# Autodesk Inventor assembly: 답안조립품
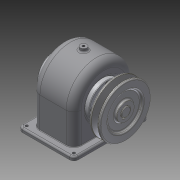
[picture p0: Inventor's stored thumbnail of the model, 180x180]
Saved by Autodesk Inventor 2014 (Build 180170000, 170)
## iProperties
Created: 2016-01
Part Number: 답안조립품
Document SubType Name: Assembly
Designer: basic
Author: basic
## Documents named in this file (16)
- C:\Users\basic\Desktop\460106V1033\답안조립품.iam
- C:\Users\basic\Desktop\460106V1033\본체.ipt
- C:\Users\basic\Desktop\460106V1033\베어링 6203.ipt
- C:\Users\basic\Desktop\460106V1033\축.ipt
- C:\Users\basic\Desktop\460106V1033\키 - 5 x 5 x 18.ipt
- C:\Users\basic\Desktop\460106V1033\키 - 6 x 6 x 22.ipt
- C:\Users\basic\Desktop\460106V1033\앞커버.ipt
- C:\Users\basic\Desktop\460106V1033\뒤커버.ipt
- C:\Users\basic\Desktop\460106V1033\부시1.ipt
- C:\Users\basic\Desktop\460106V1033\부시2.ipt
- C:\Users\basic\Desktop\460106V1033\오일씰 28 40 8.ipt
- C:\Users\basic\Desktop\460106V1033\스퍼기어.ipt
- C:\Users\basic\Desktop\460106V1033\V-벨트풀리.ipt
- C:\Users\basic\Desktop\460106V1033\멈춤나사 - M4x10.ipt
- C:\Users\basic\Desktop\460106V1033\볼트 M3 x 10.ipt
- C:\Users\basic\Desktop\460106V1033\볼트 M3 x 8.ipt
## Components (9 placed, 3 different names)
1. V-벨트풀리:1
2. ISO 4762 M3 x 10:1
3. ISO 4762 M3 x 10:2
4. ISO 4762 M3 x 10:3
5. ISO 4762 M3 x 10:4
6. ISO 4762 M3 x 8:1
7. ISO 4762 M3 x 8:2
8. ISO 4762 M3 x 8:3
9. ISO 4762 M3 x 8:4
